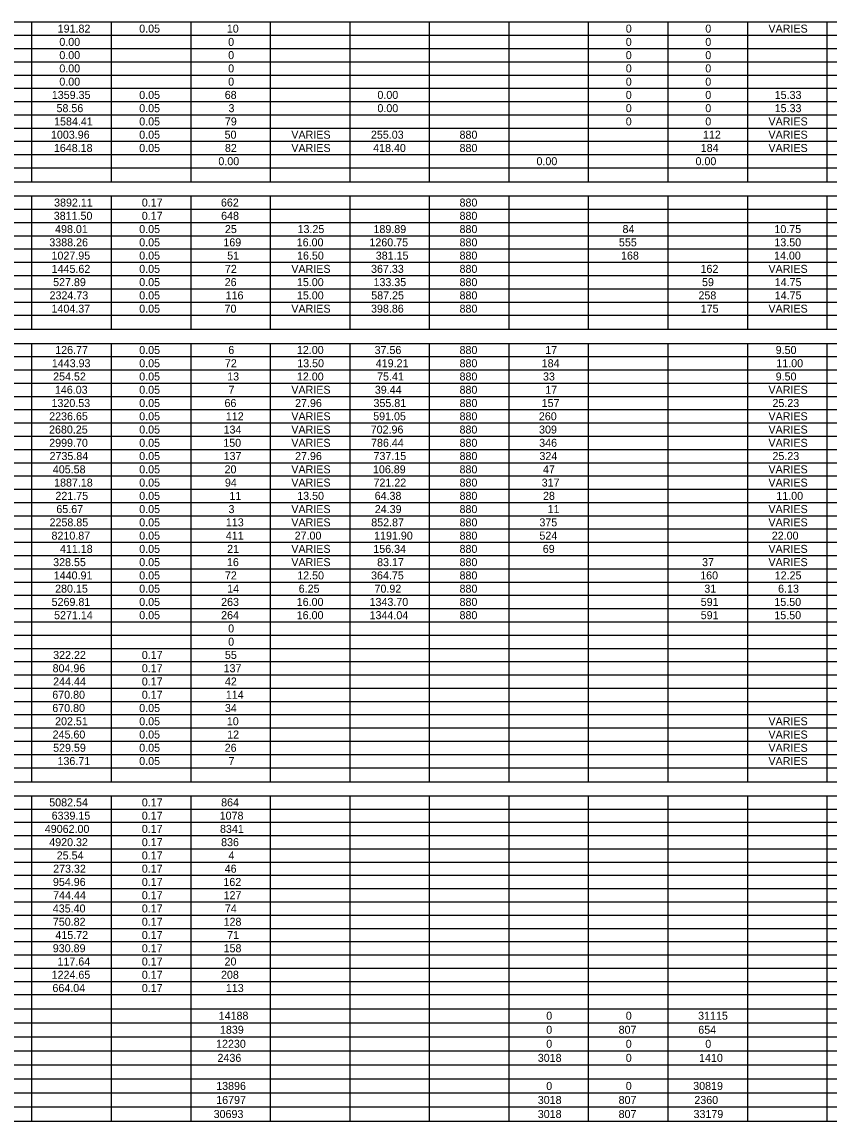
# Model space of a CAD drawing. Extents: x 1226590 to 1228573, y 151304 to 154224.
# Drawn here: x 1227125 to 1227629, y 152628 to 153315 of the extents above; entities that cross this region are included whole.
import ezdxf

# ---------------------------------------------------------------- set-up
doc = ezdxf.new("R2010")
doc.units = 0
doc.layers.add('R_Dimension', color=7, linetype='Continuous')

msp = doc.modelspace()

# ---------------------------------------------------------------- linework, layer by layer
at = {"layer": 'R_Dimension'}
for p, q in [((1226590.27, 153314.5), (1228572.93, 153314.5)), ((1227130.91, 153214.57), (1227130.91, 153314.5)), ((1227180.63, 153214.57), (1227180.63, 153314.5)), ((1227230.36, 153214.57), (1227230.36, 153314.5)), ((1227280.08, 153214.57), (1227280.08, 153314.5)), ((1227329.81, 153214.57), (1227329.81, 153314.5)), ((1227379.53, 153214.57), (1227379.53, 153314.5)), ((1227429.26, 153214.57), (1227429.26, 153314.5)), ((1227478.98, 153214.57), (1227478.98, 153314.5)), ((1227528.71, 153214.57), (1227528.71, 153314.5)), ((1227578.43, 153214.57), (1227578.43, 153314.5)), ((1227628.16, 153214.57), (1227628.16, 153314.5)), ((1226590.27, 153306.22), (1228572.93, 153306.22)), ((1226590.27, 153297.93), (1228572.93, 153297.93)), ((1226590.27, 153289.64), (1228572.93, 153289.64)), ((1226590.27, 153281.35), (1228572.93, 153281.35)), ((1226590.27, 153273.07), (1228572.93, 153273.07)), ((1226590.27, 153264.78), (1228572.93, 153264.78)), ((1226590.27, 153256.49), (1228572.93, 153256.49)), ((1226590.27, 153248.2), (1228572.93, 153248.2)), ((1226590.27, 153239.92), (1228572.93, 153239.92)), ((1226590.27, 153231.63), (1228572.93, 153231.63)), ((1226590.27, 153223.34), (1228572.93, 153223.34)), ((1226590.27, 153214.57), (1228572.93, 153214.57)), ((1226590.27, 153205.79), (1228572.93, 153205.79)), ((1227130.91, 153122.43), (1227130.91, 153205.79)), ((1227180.63, 153122.43), (1227180.63, 153205.79)), ((1227230.36, 153122.43), (1227230.36, 153205.79)), ((1227280.08, 153122.43), (1227280.08, 153205.79)), ((1227329.81, 153122.43), (1227329.81, 153205.79)), ((1227379.53, 153122.43), (1227379.53, 153205.79)), ((1227429.26, 153122.43), (1227429.26, 153205.79)), ((1227478.98, 153122.43), (1227478.98, 153205.79)), ((1227528.71, 153122.43), (1227528.71, 153205.79)), ((1227578.43, 153122.43), (1227578.43, 153205.79)), ((1227628.16, 153122.43), (1227628.16, 153205.79)), ((1226590.27, 153197.5), (1228572.93, 153197.5)), ((1226590.27, 153189.22), (1228572.93, 153189.22)), ((1226590.27, 153180.93), (1228572.93, 153180.93)), ((1226590.27, 153172.64), (1228572.93, 153172.64)), ((1226590.27, 153164.35), (1228572.93, 153164.35)), ((1226590.27, 153156.07), (1228572.93, 153156.07)), ((1226590.27, 153147.78), (1228572.93, 153147.78)), ((1226590.27, 153139.49), (1228572.93, 153139.49)), ((1226590.27, 153131.2), (1228572.93, 153131.2)), ((1226590.27, 153122.43), (1228572.93, 153122.43)), ((1226590.27, 153113.65), (1228572.93, 153113.65)), ((1227130.91, 152839.68), (1227130.91, 153113.65)), ((1227180.63, 152839.68), (1227180.63, 153113.65)), ((1227230.36, 152839.68), (1227230.36, 153113.65)), ((1227280.08, 152839.68), (1227280.08, 153113.65)), ((1227329.81, 152839.68), (1227329.81, 153113.65)), ((1227379.53, 152839.68), (1227379.53, 153113.65)), ((1227429.26, 152839.68), (1227429.26, 153113.65)), ((1227478.98, 152839.68), (1227478.98, 153113.65)), ((1227528.71, 152839.68), (1227528.71, 153113.65)), ((1227578.43, 152839.68), (1227578.43, 153113.65)), ((1227628.16, 152839.68), (1227628.16, 153113.65)), ((1226590.27, 153105.37), (1228572.93, 153105.37)), ((1226590.27, 153097.08), (1228572.93, 153097.08)), ((1226590.27, 153088.79), (1228572.93, 153088.79)), ((1226590.27, 153080.5), (1228572.93, 153080.5)), ((1226590.27, 153072.22), (1228572.93, 153072.22)), ((1226590.27, 153063.93), (1228572.93, 153063.93)), ((1226590.27, 153055.64), (1228572.93, 153055.64)), ((1226590.27, 153047.35), (1228572.93, 153047.35)), ((1226590.27, 153039.07), (1228572.93, 153039.07)), ((1226590.27, 153030.78), (1228572.93, 153030.78)), ((1226590.27, 153022.49), (1228572.93, 153022.49)), ((1226590.27, 153014.2), (1228572.93, 153014.2)), ((1226590.27, 153005.92), (1228572.93, 153005.92)), ((1226590.27, 152997.63), (1228572.93, 152997.63)), ((1226590.27, 152989.34), (1228572.93, 152989.34)), ((1226590.27, 152981.05), (1228572.93, 152981.05)), ((1226590.27, 152972.77), (1228572.93, 152972.77)), ((1226590.27, 152964.48), (1228572.93, 152964.48)), ((1226590.27, 152956.19), (1228572.93, 152956.19)), ((1226590.27, 152947.9), (1228572.93, 152947.9)), ((1226590.27, 152939.62), (1228572.93, 152939.62)), ((1226590.27, 152931.33), (1228572.93, 152931.33)), ((1226590.27, 152923.04), (1228572.93, 152923.04)), ((1226590.27, 152914.75), (1228572.93, 152914.75)), ((1226590.27, 152906.47), (1228572.93, 152906.47)), ((1226590.27, 152898.18), (1228572.93, 152898.18)), ((1226590.27, 152889.89), (1228572.93, 152889.89)), ((1226590.27, 152881.6), (1228572.93, 152881.6)), ((1226590.27, 152873.32), (1228572.93, 152873.32)), ((1226590.27, 152865.03), (1228572.93, 152865.03)), ((1226590.27, 152856.74), (1228572.93, 152856.74)), ((1226590.27, 152848.45), (1228572.93, 152848.45)), ((1226590.27, 152839.68), (1228572.93, 152839.68)), ((1226590.27, 152830.9), (1228572.93, 152830.9)), ((1227130.91, 152627.62), (1227130.91, 152830.9)), ((1227180.63, 152627.62), (1227180.63, 152830.9)), ((1227230.36, 152627.62), (1227230.36, 152830.9)), ((1227280.08, 152627.62), (1227280.08, 152830.9)), ((1227329.81, 152627.62), (1227329.81, 152830.9)), ((1227379.53, 152627.62), (1227379.53, 152830.9)), ((1227429.26, 152627.62), (1227429.26, 152830.9)), ((1227478.98, 152627.62), (1227478.98, 152830.9)), ((1227528.71, 152627.62), (1227528.71, 152830.9)), ((1227578.43, 152627.62), (1227578.43, 152830.9)), ((1227628.16, 152627.62), (1227628.16, 152830.9)), ((1226590.27, 152822.62), (1228572.93, 152822.62)), ((1226590.27, 152814.33), (1228572.93, 152814.33)), ((1226590.27, 152806.04), (1228572.93, 152806.04)), ((1226590.27, 152797.75), (1228572.93, 152797.75)), ((1226590.27, 152789.47), (1228572.93, 152789.47)), ((1226590.27, 152781.18), (1228572.93, 152781.18)), ((1226590.27, 152772.89), (1228572.93, 152772.89)), ((1226590.27, 152764.6), (1228572.93, 152764.6)), ((1226590.27, 152756.32), (1228572.93, 152756.32)), ((1226590.27, 152748.03), (1228572.93, 152748.03)), ((1226590.27, 152739.74), (1228572.93, 152739.74)), ((1226590.27, 152731.45), (1228572.93, 152731.45)), ((1226590.27, 152723.17), (1228572.93, 152723.17)), ((1226590.27, 152714.88), (1228572.93, 152714.88)), ((1226590.27, 152706.59), (1228572.93, 152706.59)), ((1226590.27, 152697.82), (1228572.93, 152697.82)), ((1226590.27, 152689.04), (1228572.93, 152689.04)), ((1226590.27, 152680.27), (1228572.93, 152680.27)), ((1226590.27, 152671.49), (1228572.93, 152671.49)), ((1226590.27, 152662.72), (1228572.93, 152662.72)), ((1226590.27, 152653.94), (1228572.93, 152653.94)), ((1226590.27, 152645.17), (1228572.93, 152645.17)), ((1226590.27, 152636.39), (1228572.93, 152636.39)), ((1226590.27, 152627.62), (1228572.93, 152627.62))]:
    msp.add_line(p, q, dxfattribs=at)

# ---------------------------------------------------------------- texts
for s, p in [('191.82', (1227146.99, 153307.86)), ('0.05', (1227197.98, 153307.86)), ('10', (1227252.76, 153307.86)), ('0', (1227502.21, 153307.86)), ('0', (1227551.94, 153307.86)), ('VARIES', (1227591.44, 153307.86)), ('0.00', (1227148.03, 153299.57)), ('0', (1227253.59, 153299.57)), ('0', (1227502.21, 153299.57)), ('0', (1227551.94, 153299.57)), ('0.00', (1227148.03, 153291.29)), ('0', (1227253.59, 153291.29)), ('0', (1227502.21, 153291.29)), ('0', (1227551.94, 153291.29)), ('0.00', (1227148.03, 153283)), ('0', (1227253.59, 153283)), ('0', (1227502.21, 153283)), ('0', (1227551.94, 153283)), ('0.00', (1227148.03, 153274.71)), ('0', (1227253.59, 153274.71)), ('0', (1227502.21, 153274.71)), ('0', (1227551.94, 153274.71)), ('1359.35', (1227143.33, 153266.42)), ('0.05', (1227197.98, 153266.42)), ('68', (1227251.44, 153266.42)), ('0.00', (1227346.93, 153266.42)), ('0', (1227502.21, 153266.42)), ('0', (1227551.94, 153266.42)), ('15.33', (1227595.34, 153266.42)), ('58.56', (1227146.26, 153258.14)), ('0.05', (1227197.98, 153258.14)), ('3', (1227253.8, 153258.14)), ('0.00', (1227346.93, 153258.14)), ('0', (1227502.21, 153258.14)), ('0', (1227551.94, 153258.14)), ('15.33', (1227595.34, 153258.14)), ('1584.41', (1227144.75, 153249.85)), ('0.05', (1227197.98, 153249.85)), ('79', (1227251.54, 153249.85)), ('0', (1227502.21, 153249.85)), ('0', (1227551.94, 153249.85)), ('VARIES', (1227591.44, 153249.85)), ('1003.96', (1227142.8, 153241.56)), ('0.05', (1227197.98, 153241.56)), ('50', (1227251.34, 153241.56)), ('VARIES', (1227293.09, 153241.56)), ('255.03', (1227342.86, 153241.56)), ('880', (1227398.27, 153241.56)), ('112', (1227550.5, 153241.56)), ('VARIES', (1227591.44, 153241.56)), ('1648.18', (1227144.63, 153233.27)), ('0.05', (1227197.98, 153233.27)), ('82', (1227251.56, 153233.27)), ('VARIES', (1227293.09, 153233.27)), ('418.40', (1227344.26, 153233.27)), ('880', (1227398.27, 153233.27)), ('184', (1227549.08, 153233.27)), ('VARIES', (1227591.44, 153233.27)), ('0.00', (1227247.48, 153224.99)), ('0.00', (1227446.38, 153224.99)), ('0.00', (1227545.83, 153224.99)), ('3892.11', (1227144.75, 153199.15)), ('0.17', (1227199.59, 153199.15)), ('662', (1227249.08, 153199.15)), ('880', (1227398.27, 153199.15)), ('3811.50', (1227144.53, 153190.86)), ('0.17', (1227199.59, 153190.86)), ('648', (1227249.2, 153190.86)), ('880', (1227398.27, 153190.86)), ('498.01', (1227145.38, 153182.57)), ('0.05', (1227197.98, 153182.57)), ('25', (1227251.56, 153182.57)), ('13.25', (1227296.99, 153182.57)), ('189.89', (1227344.45, 153182.57)), ('880', (1227398.27, 153182.57)), ('84', (1227500.18, 153182.57)), ('10.75', (1227595.15, 153182.57)), ('3388.26', (1227141.77, 153174.29)), ('0.05', (1227197.98, 153174.29)), ('169', (1227250.59, 153174.29)), ('16.00', (1227296.46, 153174.29)), ('1260.75', (1227341.91, 153174.29)), ('880', (1227398.27, 153174.29)), ('555', (1227497.94, 153174.29)), ('13.50', (1227595.13, 153174.29)), ('1027.95', (1227143.13, 153166)), ('0.05', (1227197.98, 153166)), ('51', (1227252.98, 153166)), ('16.50', (1227296.66, 153166)), ('381.15', (1227345.89, 153166)), ('880', (1227398.27, 153166)), ('168', (1227499.24, 153166)), ('14.00', (1227594.93, 153166)), ('1445.62', (1227143.21, 153157.71)), ('0.05', (1227197.98, 153157.71)), ('72', (1227251.56, 153157.71)), ('VARIES', (1227293.09, 153157.71)), ('367.33', (1227342.94, 153157.71)), ('880', (1227398.27, 153157.71)), ('162', (1227548.96, 153157.71)), ('VARIES', (1227591.44, 153157.71)), ('527.89', (1227144.14, 153149.42)), ('0.05', (1227197.98, 153149.42)), ('26', (1227251.42, 153149.42)), ('15.00', (1227296.58, 153149.42)), ('133.35', (1227344.47, 153149.42)), ('880', (1227398.27, 153149.42)), ('59', (1227549.89, 153149.42)), ('14.75', (1227595.34, 153149.42)), ('2324.73', (1227141.91, 153141.14)), ('0.05', (1227197.98, 153141.14)), ('116', (1227252.01, 153141.14)), ('15.00', (1227296.58, 153141.14)), ('587.25', (1227343.06, 153141.14)), ('880', (1227398.27, 153141.14)), ('258', (1227547.66, 153141.14)), ('14.75', (1227595.34, 153141.14)), ('1404.37', (1227143.13, 153132.85)), ('0.05', (1227197.98, 153132.85)), ('70', (1227251.34, 153132.85)), ('VARIES', (1227293.09, 153132.85)), ('398.86', (1227342.92, 153132.85)), ('880', (1227398.27, 153132.85)), ('175', (1227549.08, 153132.85)), ('VARIES', (1227591.44, 153132.85)), ('126.77', (1227145.46, 153107.01)), ('0.05', (1227197.98, 153107.01)), ('6', (1227253.67, 153107.01)), ('12.00', (1227296.58, 153107.01)), ('37.56', (1227345.16, 153107.01)), ('880', (1227398.27, 153107.01)), ('17', (1227451.88, 153107.01)), ('9.50', (1227595.95, 153107.01)), ('1443.93', (1227143.33, 153098.72)), ('0.05', (1227197.98, 153098.72)), ('72', (1227251.56, 153098.72)), ('13.50', (1227296.78, 153098.72)), ('419.21', (1227345.89, 153098.72)), ('880', (1227398.27, 153098.72)), ('184', (1227449.63, 153098.72)), ('11.00', (1227596.35, 153098.72)), ('254.52', (1227144.16, 153090.44)), ('0.05', (1227197.98, 153090.44)), ('13', (1227252.98, 153090.44)), ('12.00', (1227296.58, 153090.44)), ('75.41', (1227346.72, 153090.44)), ('880', (1227398.27, 153090.44)), ('33', (1227450.46, 153090.44)), ('9.50', (1227595.95, 153090.44)), ('146.03', (1227145.26, 153082.15)), ('0.05', (1227197.98, 153082.15)), ('7', (1227253.8, 153082.15)), ('VARIES', (1227293.09, 153082.15)), ('39.44', (1227345.3, 153082.15)), ('880', (1227398.27, 153082.15)), ('17', (1227451.88, 153082.15)), ('VARIES', (1227591.44, 153082.15)), ('1320.53', (1227143.13, 153073.86)), ('0.05', (1227197.98, 153073.86)), ('66', (1227251.3, 153073.86)), ('27.96', (1227295.44, 153073.86)), ('355.81', (1227344.47, 153073.86)), ('880', (1227398.27, 153073.86)), ('157', (1227449.63, 153073.86)), ('25.23', (1227593.93, 153073.86)), ('2236.65', (1227141.68, 153065.57)), ('0.05', (1227197.98, 153065.57)), ('112', (1227252.15, 153065.57)), ('VARIES', (1227293.09, 153065.57)), ('591.05', (1227344.28, 153065.57)), ('880', (1227398.27, 153065.57)), ('260', (1227447.88, 153065.57)), ('VARIES', (1227591.44, 153065.57)), ('2680.25', (1227141.6, 153057.29)), ('0.05', (1227197.98, 153057.29)), ('134', (1227250.73, 153057.29)), ('VARIES', (1227293.09, 153057.29)), ('702.96', (1227342.72, 153057.29)), ('880', (1227398.27, 153057.29)), ('309', (1227448, 153057.29)), ('VARIES', (1227591.44, 153057.29)), ('2999.70', (1227141.7, 153049)), ('0.05', (1227197.98, 153049)), ('150', (1227250.52, 153049)), ('VARIES', (1227293.09, 153049)), ('786.44', (1227342.94, 153049)), ('880', (1227398.27, 153049)), ('346', (1227448.08, 153049)), ('VARIES', (1227591.44, 153049)), ('2735.84', (1227141.91, 153040.71)), ('0.05', (1227197.98, 153040.71)), ('137', (1227250.73, 153040.71)), ('27.96', (1227295.44, 153040.71)), ('737.15', (1227344.47, 153040.71)), ('880', (1227398.27, 153040.71)), ('324', (1227448.21, 153040.71)), ('25.23', (1227593.93, 153040.71)), ('405.58', (1227143.96, 153032.42)), ('0.05', (1227197.98, 153032.42)), ('20', (1227251.34, 153032.42)), ('VARIES', (1227293.09, 153032.42)), ('106.89', (1227344.14, 153032.42)), ('880', (1227398.27, 153032.42)), ('47', (1227450.46, 153032.42)), ('VARIES', (1227591.44, 153032.42)), ('1887.18', (1227144.75, 153024.14)), ('0.05', (1227197.98, 153024.14)), ('94', (1227251.56, 153024.14)), ('VARIES', (1227293.09, 153024.14)), ('721.22', (1227344.47, 153024.14)), ('880', (1227398.27, 153024.14)), ('317', (1227449.63, 153024.14)), ('VARIES', (1227591.44, 153024.14)), ('221.75', (1227145.57, 153015.85)), ('0.05', (1227197.98, 153015.85)), ('11', (1227254.39, 153015.85)), ('13.50', (1227296.78, 153015.85)), ('64.38', (1227345.18, 153015.85)), ('880', (1227398.27, 153015.85)), ('28', (1227450.46, 153015.85)), ('11.00', (1227596.35, 153015.85)), ('65.67', (1227146.16, 153007.56)), ('0.05', (1227197.98, 153007.56)), ('3', (1227253.8, 153007.56)), ('VARIES', (1227293.09, 153007.56)), ('24.39', (1227345.28, 153007.56)), ('880', (1227398.27, 153007.56)), ('11', (1227453.29, 153007.56)), ('VARIES', (1227591.44, 153007.56)), ('2258.85', (1227141.91, 152999.27)), ('0.05', (1227197.98, 152999.27)), ('113', (1227252.15, 152999.27)), ('VARIES', (1227293.09, 152999.27)), ('852.87', (1227343.06, 152999.27)), ('880', (1227398.27, 152999.27)), ('375', (1227448.21, 152999.27)), ('VARIES', (1227591.44, 152999.27)), ('8210.87', (1227143.13, 152990.99)), ('0.05', (1227197.98, 152990.99)), ('411', (1227252.15, 152990.99)), ('27.00', (1227295.16, 152990.99)), ('1191.90', (1227344.85, 152990.99)), ('880', (1227398.27, 152990.99)), ('524', (1227448.21, 152990.99)), ('22.00', (1227593.51, 152990.99)), ('411.18', (1227148.41, 152982.7)), ('0.05', (1227197.98, 152982.7)), ('21', (1227252.98, 152982.7)), ('VARIES', (1227293.09, 152982.7)), ('156.34', (1227344.36, 152982.7)), ('880', (1227398.27, 152982.7)), ('69', (1227450.32, 152982.7)), ('VARIES', (1227591.44, 152982.7)), ('328.55', (1227144.16, 152974.41)), ('0.05', (1227197.98, 152974.41)), ('16', (1227252.84, 152974.41)), ('VARIES', (1227293.09, 152974.41)), ('83.17', (1227346.72, 152974.41)), ('880', (1227398.27, 152974.41)), ('37', (1227549.91, 152974.41)), ('VARIES', (1227591.44, 152974.41)), ('1440.91', (1227144.55, 152966.12)), ('0.05', (1227197.98, 152966.12)), ('72', (1227251.56, 152966.12)), ('12.50', (1227296.78, 152966.12)), ('364.75', (1227342.94, 152966.12)), ('880', (1227398.27, 152966.12)), ('160', (1227548.75, 152966.12)), ('12.25', (1227595.34, 152966.12)), ('280.15', (1227145.38, 152957.84)), ('0.05', (1227197.98, 152957.84)), ('14', (1227252.98, 152957.84)), ('6.25', (1227297.7, 152957.84)), ('70.92', (1227345.1, 152957.84)), ('880', (1227398.27, 152957.84)), ('31', (1227551.33, 152957.84)), ('6.13', (1227597.47, 152957.84)), ('5269.81', (1227143.21, 152949.55)), ('0.05', (1227197.98, 152949.55)), ('263', (1227249.2, 152949.55)), ('16.00', (1227296.46, 152949.55)), ('1343.70', (1227342.01, 152949.55)), ('880', (1227398.27, 152949.55)), ('591', (1227549.08, 152949.55)), ('15.50', (1227595.13, 152949.55)), ('5271.14', (1227144.75, 152941.26)), ('0.05', (1227197.98, 152941.26)), ('264', (1227249.2, 152941.26)), ('16.00', (1227296.46, 152941.26)), ('1344.04', (1227342.03, 152941.26)), ('880', (1227398.27, 152941.26)), ('591', (1227549.08, 152941.26)), ('15.50', (1227595.13, 152941.26)), ('0', (1227253.59, 152932.97)), ('0', (1227253.59, 152924.69)), ('322.22', (1227144.16, 152916.4)), ('0.17', (1227199.59, 152916.4)), ('55', (1227251.56, 152916.4)), ('804.96', (1227143.82, 152908.11)), ('0.17', (1227199.59, 152908.11)), ('137', (1227250.73, 152908.11)), ('244.44', (1227144.16, 152899.82)), ('0.17', (1227199.59, 152899.82)), ('42', (1227251.56, 152899.82)), ('670.80', (1227143.62, 152891.54)), ('0.17', (1227199.59, 152891.54)), ('114', (1227252.15, 152891.54)), ('670.80', (1227143.62, 152883.25)), ('0.05', (1227197.98, 152883.25)), ('34', (1227251.56, 152883.25)), ('202.51', (1227145.38, 152874.96)), ('0.05', (1227197.98, 152874.96)), ('10', (1227252.76, 152874.96)), ('VARIES', (1227591.44, 152874.96)), ('245.60', (1227143.82, 152866.67)), ('0.05', (1227197.98, 152866.67)), ('12', (1227252.98, 152866.67)), ('VARIES', (1227591.44, 152866.67)), ('529.59', (1227144.14, 152858.39)), ('0.05', (1227197.98, 152858.39)), ('26', (1227251.42, 152858.39)), ('VARIES', (1227591.44, 152858.39)), ('136.71', (1227146.87, 152850.1)), ('0.05', (1227197.98, 152850.1)), ('7', (1227253.8, 152850.1)), ('VARIES', (1227591.44, 152850.1)), ('5082.54', (1227141.72, 152824.26)), ('0.17', (1227199.59, 152824.26)), ('864', (1227249.2, 152824.26)), ('6339.15', (1227143.21, 152815.97)), ('0.17', (1227199.59, 152815.97)), ('1078', (1227248.29, 152815.97)), ('49062.00', (1227138.94, 152807.69)), ('0.17', (1227199.59, 152807.69)), ('8341', (1227248.49, 152807.69)), ('4920.32', (1227141.72, 152799.4)), ('0.17', (1227199.59, 152799.4)), ('836', (1227249.18, 152799.4)), ('25.54', (1227146.4, 152791.11)), ('0.17', (1227199.59, 152791.11)), ('4', (1227253.8, 152791.11)), ('273.32', (1227144.16, 152782.82)), ('0.17', (1227199.59, 152782.82)), ('46', (1227251.42, 152782.82)), ('954.96', (1227144.02, 152774.54)), ('0.17', (1227199.59, 152774.54)), ('162', (1227250.61, 152774.54)), ('744.44', (1227144.16, 152766.25)), ('0.17', (1227199.59, 152766.25)), ('127', (1227250.73, 152766.25)), ('435.40', (1227143.94, 152757.96)), ('0.17', (1227199.59, 152757.96)), ('74', (1227251.56, 152757.96)), ('750.82', (1227143.96, 152749.67)), ('0.17', (1227199.59, 152749.67)), ('128', (1227250.73, 152749.67)), ('415.72', (1227145.57, 152741.39)), ('0.17', (1227199.59, 152741.39)), ('71', (1227252.98, 152741.39)), ('930.89', (1227143.94, 152733.1)), ('0.17', (1227199.59, 152733.1)), ('158', (1227250.73, 152733.1)), ('117.64', (1227146.87, 152724.81)), ('0.17', (1227199.59, 152724.81)), ('20', (1227251.34, 152724.81)), ('1224.65', (1227143.21, 152716.52)), ('0.17', (1227199.59, 152716.52)), ('208', (1227249.12, 152716.52)), ('664.04', (1227143.72, 152708.24)), ('0.17', (1227199.59, 152708.24)), ('113', (1227252.15, 152708.24)), ('14188', (1227247.66, 152690.93)), ('0', (1227452.49, 152690.93)), ('0', (1227502.21, 152690.93)), ('31115', (1227547.43, 152690.93)), ('1839', (1227248.47, 152682.15)), ('0', (1227452.49, 152682.15)), ('807', (1227497.74, 152682.15)), ('654', (1227547.55, 152682.15)), ('12230', (1227246.03, 152673.38)), ('0', (1227452.49, 152673.38)), ('0', (1227502.21, 152673.38)), ('0', (1227551.94, 152673.38)), ('2436', (1227246.93, 152664.6)), ('3018', (1227447.19, 152664.6)), ('0', (1227502.21, 152664.6)), ('1410', (1227548.04, 152664.6)), ('13896', (1227246.11, 152647.05)), ('0', (1227452.49, 152647.05)), ('0', (1227502.21, 152647.05)), ('30819', (1227544.38, 152647.05)), ('16797', (1227246.13, 152638.28)), ('3018', (1227447.19, 152638.28)), ('807', (1227497.74, 152638.28)), ('2360', (1227545.09, 152638.28)), ('30693', (1227244.51, 152629.5)), ('3018', (1227447.19, 152629.5)), ('807', (1227497.74, 152629.5)), ('33179', (1227544.57, 152629.5))]:
    msp.add_text(s, height=5, dxfattribs=at).set_placement(p)

doc.saveas('drawing.dxf')
